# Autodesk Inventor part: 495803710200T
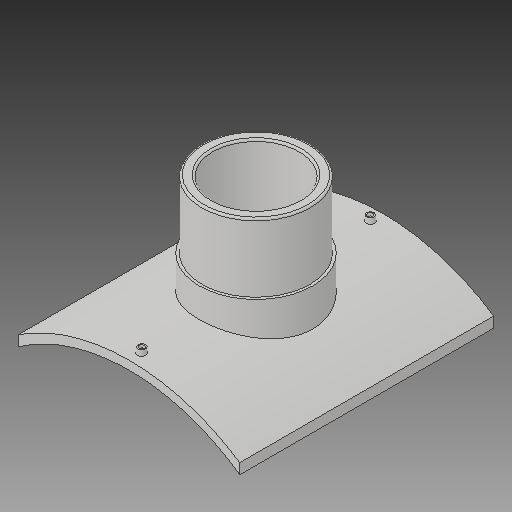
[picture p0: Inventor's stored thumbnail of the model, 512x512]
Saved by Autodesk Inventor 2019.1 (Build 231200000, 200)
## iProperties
Created: 2017-10
Part Number: 495803710200T
Material: Generic
Description: PLASSON BRANCH SADDLE  710x200
Document SubType Name: Modeling
Designer: KIM
Mass: 2754.05 g
Surface Area: 3037.44 cm^2
Volume: 2754.05 cm^3
Density: 1 g/cm^3
Appearance: Default
Author: KIM
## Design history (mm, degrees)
derived "495803.ipt"
feature "Solid1::495803.ipt"
tag "TaggingFeature1"
body "Solid1"
other parameters: "d1" = 16, "d4" = 0, "d12" = 380.6, "d13" = 14, "d14" = 211.5, "d16" = 5 deg, "d18" = 4, "d19" = 14, "d20" = 0, "d21" = 3, "d22" = 0, "d23" = 551, "d25" = 16, "d28" = 0, "d29" = 9.6, "d31" = 0, "d33" = 0, "d34" = 7.1, "d37" = 126, "d38" = 0, "d39" = 3.55, "x_" = 16, "D_" = 16
